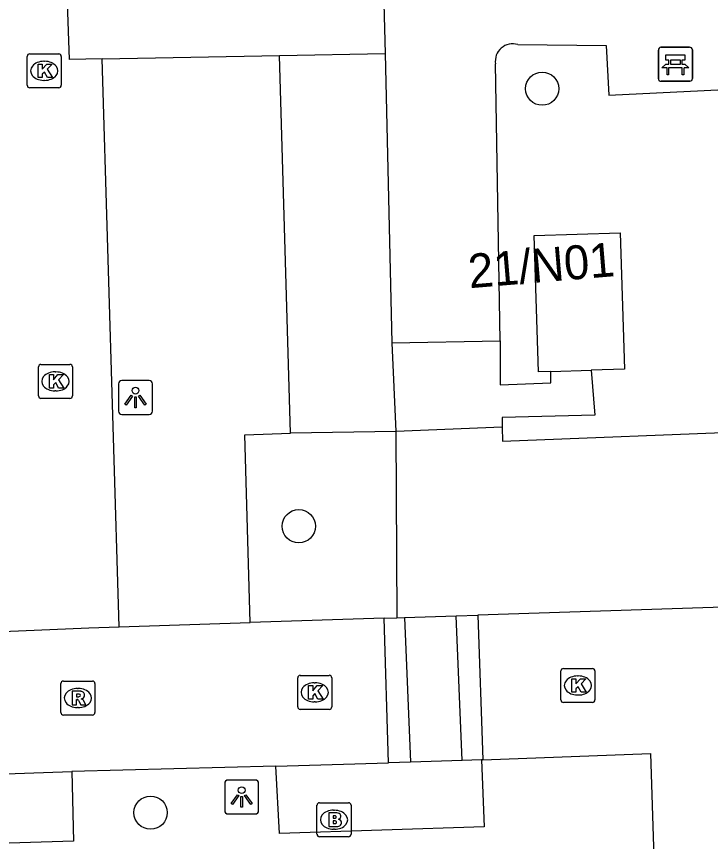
# Model space of a CAD drawing. Extents: x 162250 to 162654, y 380744 to 381605.
# Drawn here: x 162372.82 to 162393.23, y 381114.47 to 381138.73 of the extents above; entities that cross this region are included whole.
import ezdxf

# ---------------------------------------------------------------- set-up
doc = ezdxf.new("R2010")
doc.units = 0
for name, color, linetype in [('IMGEO_Bank', 7, 'Continuous'), ('IMGEO_Boom', 7, 'Continuous'), ('IMGEO_Brandkraan', 7, 'Continuous'), ('IMGEO_Groenvoorziening', 7, 'Continuous'), ('IMGEO_Kolk', 7, 'Continuous'), ('IMGEO_Lichtpunt', 7, 'Continuous'), ('IMGEO_Pand', 7, 'Continuous'), ('IMGEO_Pand_nummerreeks', 7, 'Continuous'), ('IMGEO_Parkeervlak_open', 7, 'Continuous'), ('IMGEO_Rioolput', 7, 'Continuous'), ('IMGEO_Voetpad_gesloten', 7, 'Continuous'), ('IMGEO_Voetpad_open', 7, 'Continuous'), ('IMGEO_Woonerf_open', 7, 'Continuous')]:
    doc.layers.add(name, color=color, linetype=linetype)

msp = doc.modelspace()

# ---------------------------------------------------------------- linework, layer by layer
at = {"layer": 'IMGEO_Bank'}
for p, q in [((162391.773, 381137.826), (162392.614, 381137.826)), ((162392.614, 381137.826), (162391.773, 381137.826)), ((162391.698, 381136.901), (162391.698, 381137.742)), ((162391.698, 381137.742), (162391.698, 381136.901)), ((162392.698, 381137.751), (162392.698, 381136.91)), ((162392.698, 381136.91), (162392.698, 381137.751)), ((162392.007, 381137.332), (162392.007, 381137.438)), ((162392.051, 381137.438), (162392.051, 381137.332)), ((162392.339, 381137.444), (162392.057, 381137.444)), ((162392.057, 381137.326), (162392.339, 381137.326)), ((162392.345, 381137.332), (162392.345, 381137.438)), ((162392.389, 381137.438), (162392.389, 381137.332)), ((162392.395, 381137.224), (162392.002, 381137.224)), ((162392.623, 381136.826), (162391.782, 381136.826)), ((162391.782, 381136.826), (162392.623, 381136.826))]:
    msp.add_line(p, q, dxfattribs=at)
for points in [[(162392.001, 381137.444), (162391.915, 381137.444), (162391.915, 381137.605), (162392.478, 381137.605), (162392.478, 381137.444), (162392.395, 381137.444)], [(162391.945, 381137.224), (162391.803, 381137.224), (162391.915, 381137.326), (162392.001, 381137.326)], [(162392.395, 381137.326), (162392.478, 381137.326), (162392.59, 381137.224), (162392.451, 381137.224)], [(162391.995, 381137.217), (162391.995, 381137.01), (162391.952, 381137.01), (162391.952, 381137.217)], [(162392.445, 381137.217), (162392.445, 381137.01), (162392.401, 381137.01), (162392.401, 381137.217)]]:
    msp.add_lwpolyline(points, dxfattribs=at)
for centre, radius, start, end in [((162391.776, 381137.748), 0.0779, 92.4484, 184.2845), ((162391.776, 381137.748), 0.0779, 92.4484, 184.2845), ((162392.62, 381137.748), 0.0779, 2.4484, 94.2845), ((162392.62, 381137.748), 0.0779, 2.4484, 94.2845), ((162392, 381137.437), 0.00671, 2.8957, 87.1043), ((162392, 381137.333), 0.00671, 272.8957, 357.1043), ((162392.057, 381137.437), 0.00671, 92.8957, 177.1043), ((162392.057, 381137.333), 0.00671, 182.8957, 267.1043), ((162392.339, 381137.437), 0.00671, 2.8957, 87.1043), ((162392.339, 381137.333), 0.00671, 272.8957, 357.1043), ((162392.396, 381137.437), 0.00671, 92.8957, 177.1043), ((162392.396, 381137.333), 0.00671, 182.8957, 267.1043), ((162391.945, 381137.217), 0.00671, 2.8957, 87.1043), ((162392.002, 381137.217), 0.00671, 92.8957, 177.1043), ((162392.394, 381137.217), 0.00671, 2.8957, 87.1043), ((162392.451, 381137.217), 0.00671, 92.8957, 177.1043), ((162391.776, 381136.904), 0.0779, 182.4484, 274.2845), ((162391.776, 381136.904), 0.0779, 182.4484, 274.2845), ((162392.62, 381136.904), 0.0779, 272.4484, 4.2845), ((162392.62, 381136.904), 0.0779, 272.4484, 4.2845)]:
    msp.add_arc(centre, radius, start, end, dxfattribs=at)
at = {"layer": 'IMGEO_Boom'}
for centre in [(162388.281, 381136.607), (162381.124, 381123.738), (162376.767, 381115.316)]:
    msp.add_circle(centre, 0.489, dxfattribs=at)
at = {"layer": 'IMGEO_Brandkraan'}
for p, q in [((162381.66, 381114.681), (162381.66, 381115.533)), ((162381.735, 381115.607), (162382.587, 381115.607)), ((162382.661, 381115.533), (162382.661, 381114.681)), ((162382.148, 381115.387), (162382.173, 381115.387)), ((162382.171, 381114.827), (162382.146, 381114.827)), ((162382.587, 381114.607), (162381.735, 381114.607))]:
    msp.add_line(p, q, dxfattribs=at)
for points in [[(162381.66, 381114.681), (162381.66, 381115.533)], [(162381.735, 381115.607), (162382.587, 381115.607)], [(162382.661, 381115.533), (162382.661, 381114.681)], [(162382.008, 381115.307), (162382.008, 381114.907), (162382.221, 381114.907)], [(162382.239, 381115.307), (162382.008, 381115.307)], [(162382.187, 381115.226), (162382.133, 381115.226), (162382.133, 381115.15)], [(162382.133, 381115.15), (162382.186, 381115.15)], [(162382.195, 381115.074), (162382.133, 381115.074), (162382.133, 381114.993)], [(162382.133, 381114.993), (162382.195, 381114.993)], [(162382.587, 381114.607), (162381.735, 381114.607)]]:
    msp.add_lwpolyline(points, dxfattribs=at)
for centre, radius, start, end in [((162381.737, 381115.531), 0.0765, 91.552, 178.448), ((162381.737, 381115.531), 0.0765, 91.552, 178.448), ((162382.585, 381115.531), 0.0765, 1.552, 88.448), ((162382.585, 381115.531), 0.0765, 1.552, 88.448), ((162382.243, 381115.162), 0.145, 59.4692, 91.5367), ((162382.268, 381115.209), 0.0922, 285.5137, 58.1501), ((162382.188, 381115.188), 0.0379, 267.8285, 90.9355), ((162382.196, 381115.033), 0.0404, 269.8759, 90.5077), ((162382.273, 381115.017), 0.105, 301.3115, 78.989), ((162382.227, 381115.158), 0.251, 268.6676, 293.5347), ((162381.737, 381114.683), 0.0765, 181.552, 268.448), ((162381.737, 381114.683), 0.0765, 181.552, 268.448), ((162382.585, 381114.683), 0.0765, 271.552, 358.448), ((162382.585, 381114.683), 0.0765, 271.552, 358.448)]:
    msp.add_arc(centre, radius, start, end, dxfattribs=at)
for centre, major_axis, ratio, start_param, end_param in [((162382.147, 381115.107), (-0.387, 0.002), 0.722429, 4.712389, 7.853982), ((162382.172, 381115.107), (-0.39, 0.002), 0.717154, 1.570796, 4.712389)]:
    msp.add_ellipse(centre, major_axis=major_axis, ratio=ratio, start_param=start_param, end_param=end_param, dxfattribs=at)
at = {"layer": 'IMGEO_Groenvoorziening'}
msp.add_lwpolyline([(162383.975, 381126.528), (162380.885, 381126.473)], dxfattribs=at)
at = {"layer": 'IMGEO_Kolk'}
for p, q in [((162373.214, 381137.632), (162374.066, 381137.632)), ((162373.139, 381136.706), (162373.139, 381137.558)), ((162373.627, 381137.412), (162373.652, 381137.412)), ((162374.14, 381137.558), (162374.14, 381136.706)), ((162373.65, 381136.852), (162373.625, 381136.852)), ((162374.066, 381136.632), (162373.214, 381136.632)), ((162373.47, 381127.572), (162373.47, 381128.424)), ((162373.545, 381128.498), (162374.397, 381128.498)), ((162374.471, 381128.424), (162374.471, 381127.572)), ((162373.958, 381128.278), (162373.983, 381128.278)), ((162373.981, 381127.718), (162373.956, 381127.718)), ((162374.397, 381127.498), (162373.545, 381127.498)), ((162388.831, 381118.63), (162388.831, 381119.482)), ((162388.906, 381119.556), (162389.758, 381119.556)), ((162389.832, 381119.482), (162389.832, 381118.63)), ((162381.093, 381118.428), (162381.093, 381119.28)), ((162381.168, 381119.354), (162382.02, 381119.354)), ((162381.581, 381119.134), (162381.606, 381119.134)), ((162382.094, 381119.28), (162382.094, 381118.428)), ((162389.319, 381119.336), (162389.344, 381119.336)), ((162389.342, 381118.776), (162389.317, 381118.776)), ((162381.604, 381118.574), (162381.579, 381118.574)), ((162389.758, 381118.556), (162388.906, 381118.556)), ((162382.02, 381118.354), (162381.168, 381118.354))]:
    msp.add_line(p, q, dxfattribs=at)
for points in [[(162373.214, 381137.632), (162374.066, 381137.632)], [(162373.139, 381136.706), (162373.139, 381137.558)], [(162373.46, 381137.332), (162373.583, 381137.332), (162373.583, 381137.181), (162373.713, 381137.332), (162373.877, 381137.332), (162373.731, 381137.181), (162373.884, 381136.932), (162373.732, 381136.932), (162373.647, 381137.096), (162373.583, 381137.029), (162373.583, 381136.932), (162373.46, 381136.932), (162373.46, 381137.332)], [(162374.14, 381137.558), (162374.14, 381136.706)], [(162374.066, 381136.632), (162373.214, 381136.632)], [(162373.47, 381127.572), (162373.47, 381128.424)], [(162373.545, 381128.498), (162374.397, 381128.498)], [(162374.471, 381128.424), (162374.471, 381127.572)], [(162373.791, 381128.198), (162373.914, 381128.198), (162373.914, 381128.047), (162374.044, 381128.198), (162374.208, 381128.198), (162374.062, 381128.047), (162374.215, 381127.798), (162374.063, 381127.798), (162373.978, 381127.962), (162373.914, 381127.895), (162373.914, 381127.798), (162373.791, 381127.798), (162373.791, 381128.198)], [(162374.397, 381127.498), (162373.545, 381127.498)], [(162388.831, 381118.63), (162388.831, 381119.482)], [(162388.906, 381119.556), (162389.758, 381119.556)], [(162389.832, 381119.482), (162389.832, 381118.63)], [(162381.093, 381118.428), (162381.093, 381119.28)], [(162381.168, 381119.354), (162382.02, 381119.354)], [(162382.094, 381119.28), (162382.094, 381118.428)], [(162389.152, 381119.256), (162389.275, 381119.256), (162389.275, 381119.105), (162389.405, 381119.256), (162389.569, 381119.256), (162389.423, 381119.105), (162389.576, 381118.856), (162389.424, 381118.856), (162389.339, 381119.02), (162389.275, 381118.953), (162389.275, 381118.856), (162389.152, 381118.856), (162389.152, 381119.256)], [(162381.414, 381119.054), (162381.537, 381119.054), (162381.537, 381118.903), (162381.667, 381119.054), (162381.831, 381119.054), (162381.685, 381118.903), (162381.838, 381118.654), (162381.686, 381118.654), (162381.601, 381118.818), (162381.537, 381118.751), (162381.537, 381118.654), (162381.414, 381118.654), (162381.414, 381119.054)], [(162389.758, 381118.556), (162388.906, 381118.556)], [(162382.02, 381118.354), (162381.168, 381118.354)]]:
    msp.add_lwpolyline(points, dxfattribs=at)
for centre, start, end in [((162373.216, 381137.556), 91.552, 178.448), ((162373.216, 381137.556), 91.552, 178.448), ((162374.064, 381137.556), 1.552, 88.448), ((162374.064, 381137.556), 1.552, 88.448), ((162373.216, 381136.708), 181.552, 268.448), ((162373.216, 381136.708), 181.552, 268.448), ((162374.064, 381136.708), 271.552, 358.448), ((162374.064, 381136.708), 271.552, 358.448), ((162373.547, 381128.422), 91.552, 178.448), ((162373.547, 381128.422), 91.552, 178.448), ((162374.395, 381128.422), 1.552, 88.448), ((162374.395, 381128.422), 1.552, 88.448), ((162373.547, 381127.574), 181.552, 268.448), ((162373.547, 381127.574), 181.552, 268.448), ((162374.395, 381127.574), 271.552, 358.448), ((162374.395, 381127.574), 271.552, 358.448), ((162388.908, 381119.48), 91.552, 178.448), ((162388.908, 381119.48), 91.552, 178.448), ((162389.756, 381119.48), 1.552, 88.448), ((162389.756, 381119.48), 1.552, 88.448), ((162381.17, 381119.278), 91.552, 178.448), ((162381.17, 381119.278), 91.552, 178.448), ((162382.018, 381119.278), 1.552, 88.448), ((162382.018, 381119.278), 1.552, 88.448), ((162381.17, 381118.43), 181.552, 268.448), ((162381.17, 381118.43), 181.552, 268.448), ((162382.018, 381118.43), 271.552, 358.448), ((162382.018, 381118.43), 271.552, 358.448), ((162388.908, 381118.632), 181.552, 268.448), ((162388.908, 381118.632), 181.552, 268.448), ((162389.756, 381118.632), 271.552, 358.448), ((162389.756, 381118.632), 271.552, 358.448)]:
    msp.add_arc(centre, 0.0765, start, end, dxfattribs=at)
for centre, major_axis, ratio, start_param, end_param in [((162373.626, 381137.132), (-0.387, 0.002), 0.722429, 4.712389, 7.853982), ((162373.651, 381137.132), (-0.39, 0.002), 0.717154, 1.570796, 4.712389), ((162373.957, 381127.998), (-0.387, 0.002), 0.722429, 4.712389, 7.853982), ((162373.982, 381127.998), (-0.39, 0.002), 0.717154, 1.570796, 4.712389), ((162381.58, 381118.854), (-0.387, 0.002), 0.722429, 4.712389, 7.853982), ((162381.605, 381118.854), (-0.39, 0.002), 0.717154, 1.570796, 4.712389), ((162389.318, 381119.056), (-0.387, 0.002), 0.722429, 4.712389, 7.853982), ((162389.343, 381119.056), (-0.39, 0.002), 0.717154, 1.570796, 4.712389)]:
    msp.add_ellipse(centre, major_axis=major_axis, ratio=ratio, start_param=start_param, end_param=end_param, dxfattribs=at)
at = {"layer": 'IMGEO_Lichtpunt'}
for p, q in [((162375.825, 381127.929), (162375.825, 381127.122)), ((162375.825, 381127.929), (162375.825, 381127.122)), ((162376.727, 381128.024), (162375.919, 381128.024)), ((162376.727, 381128.024), (162375.919, 381128.024)), ((162376.821, 381127.122), (162376.821, 381127.929)), ((162376.821, 381127.122), (162376.821, 381127.929)), ((162375.919, 381127.028), (162376.727, 381127.028)), ((162375.919, 381127.028), (162376.727, 381127.028)), ((162379.849, 381116.275), (162379.041, 381116.275)), ((162379.849, 381116.275), (162379.041, 381116.275)), ((162378.947, 381116.18), (162378.947, 381115.373)), ((162378.947, 381116.18), (162378.947, 381115.373)), ((162379.943, 381115.373), (162379.943, 381116.18)), ((162379.943, 381115.373), (162379.943, 381116.18)), ((162379.041, 381115.279), (162379.849, 381115.279)), ((162379.041, 381115.279), (162379.849, 381115.279))]:
    msp.add_line(p, q, dxfattribs=at)
for points in [[(162376.199, 381127.593), (162376.238, 381127.565), (162376.05, 381127.303), (162376.012, 381127.33), (162376.199, 381127.593)], [(162376.301, 381127.545), (162376.348, 381127.545), (162376.348, 381127.223), (162376.301, 381127.223), (162376.301, 381127.545)], [(162376.411, 381127.565), (162376.449, 381127.592), (162376.636, 381127.33), (162376.597, 381127.302), (162376.411, 381127.565)], [(162379.321, 381115.844), (162379.36, 381115.816), (162379.172, 381115.554), (162379.134, 381115.581), (162379.321, 381115.844)], [(162379.423, 381115.796), (162379.47, 381115.796), (162379.47, 381115.474), (162379.423, 381115.474), (162379.423, 381115.796)], [(162379.533, 381115.816), (162379.571, 381115.843), (162379.758, 381115.581), (162379.719, 381115.553), (162379.533, 381115.816)]]:
    msp.add_lwpolyline(points, dxfattribs=at)
for centre in [(162376.324, 381127.727), (162379.446, 381115.978)]:
    msp.add_circle(centre, 0.0994, dxfattribs=at)
for centre, start, end in [((162375.919, 381127.929), 90, 180), ((162375.919, 381127.929), 90, 180), ((162376.727, 381127.929), 0, 90), ((162376.727, 381127.929), 0, 90), ((162375.919, 381127.122), 180, 270), ((162375.919, 381127.122), 180, 270), ((162376.727, 381127.122), 270, 0), ((162376.727, 381127.122), 270, 360), ((162379.041, 381116.18), 90, 180), ((162379.041, 381116.18), 90, 180), ((162379.849, 381116.18), 0, 90), ((162379.849, 381116.18), 0, 90), ((162379.041, 381115.373), 180, 270), ((162379.041, 381115.373), 180, 270), ((162379.849, 381115.373), 270, 0), ((162379.849, 381115.373), 270, 360)]:
    msp.add_arc(centre, 0.0946, start, end, dxfattribs=at)
at = {"layer": 'IMGEO_Pand'}
for points in [[(162388.535, 381128.29), (162388.172, 381128.279), (162388.045, 381132.292), (162390.576, 381132.372), (162390.703, 381128.358), (162389.723, 381128.327)], [(162388.535, 381128.29), (162389.723, 381128.327)]]:
    msp.add_lwpolyline(points, dxfattribs=at)
at = {"layer": 'IMGEO_Parkeervlak_open'}
for points in [[(162380.885, 381126.473), (162380.554, 381137.585)], [(162375.842, 381120.781), (162375.345, 381137.488)], [(162387.106, 381126.653), (162387.113, 381126.237), (162402.073, 381126.826)], [(162379.694, 381120.907), (162379.538, 381126.427), (162380.885, 381126.473)], [(162383.975, 381126.528), (162384.005, 381121.048)], [(162401.426, 381121.617), (162386.393, 381121.126)], [(162384.234, 381121.055), (162385.748, 381121.105)], [(162385.748, 381121.105), (162386.393, 381121.126)], [(162375.842, 381120.781), (162379.694, 381120.907)], [(162384.005, 381121.048), (162384.234, 381121.055)], [(162380.448, 381116.685), (162383.758, 381116.785)], [(162384.408, 381116.804), (162383.758, 381116.785)], [(162385.931, 381116.85), (162384.408, 381116.804)], [(162386.5, 381116.867), (162385.931, 381116.85)], [(162369.712, 381116.357), (162374.447, 381116.522)]]:
    msp.add_lwpolyline(points, dxfattribs=at)
at = {"layer": 'IMGEO_Rioolput'}
for p, q in [((162374.204, 381119.186), (162375.056, 381119.186)), ((162374.129, 381118.26), (162374.129, 381119.112)), ((162374.617, 381118.966), (162374.642, 381118.966)), ((162375.13, 381119.112), (162375.13, 381118.26)), ((162374.64, 381118.406), (162374.615, 381118.406)), ((162375.056, 381118.186), (162374.204, 381118.186))]:
    msp.add_line(p, q, dxfattribs=at)
for points in [[(162374.204, 381119.186), (162375.056, 381119.186)], [(162374.129, 381118.26), (162374.129, 381119.112)], [(162374.718, 381118.884), (162374.466, 381118.886), (162374.466, 381118.486)], [(162375.13, 381119.112), (162375.13, 381118.26)], [(162374.466, 381118.486), (162374.59, 381118.486), (162374.59, 381118.648), (162374.601, 381118.648)], [(162374.644, 381118.805), (162374.59, 381118.805), (162374.59, 381118.724)], [(162374.59, 381118.724), (162374.642, 381118.724)], [(162374.648, 381118.619), (162374.719, 381118.486), (162374.859, 381118.486), (162374.794, 381118.612)], [(162375.056, 381118.186), (162374.204, 381118.186)]]:
    msp.add_lwpolyline(points, dxfattribs=at)
for centre, radius, start, end in [((162374.206, 381119.11), 0.0765, 91.552, 178.448), ((162374.206, 381119.11), 0.0765, 91.552, 178.448), ((162375.054, 381119.11), 0.0765, 1.552, 88.448), ((162375.054, 381119.11), 0.0765, 1.552, 88.448), ((162374.717, 381118.774), 0.109, 350.3612, 89.416), ((162374.6, 381118.595), 0.0533, 26.0293, 88.6989), ((162374.626, 381118.913), 0.19, 274.7715, 282.9687), ((162374.65, 381118.709), 0.0964, 77.0061, 93.1865), ((162374.664, 381118.766), 0.0378, 276.6634, 79.6772), ((162374.715, 381118.774), 0.112, 277.5842, 350.9817), ((162374.699, 381118.559), 0.108, 29.5134, 73.7905), ((162374.206, 381118.262), 0.0765, 181.552, 268.448), ((162374.206, 381118.262), 0.0765, 181.552, 268.448), ((162375.054, 381118.262), 0.0765, 271.552, 358.448), ((162375.054, 381118.262), 0.0765, 271.552, 358.448)]:
    msp.add_arc(centre, radius, start, end, dxfattribs=at)
for centre, major_axis, ratio, start_param, end_param in [((162374.616, 381118.686), (-0.387, 0.002), 0.722429, 4.712389, 7.853982), ((162374.641, 381118.686), (-0.39, 0.002), 0.717154, 1.570796, 4.712389)]:
    msp.add_ellipse(centre, major_axis=major_axis, ratio=ratio, start_param=start_param, end_param=end_param, dxfattribs=at)
at = {"layer": 'IMGEO_Voetpad_gesloten'}
for points in [[(162383.599, 381140.226), (162383.661, 381137.643)], [(162387.564, 381137.904), (162390.166, 381137.88), (162390.243, 381136.417), (162397.246, 381136.763), (162397.189, 381138.232), (162401.842, 381138.323)], [(162383.661, 381137.643), (162383.865, 381129.129)], [(162387.046, 381129.195), (162386.909, 381137.336)], [(162383.865, 381129.129), (162387.046, 381129.195)]]:
    msp.add_lwpolyline(points, dxfattribs=at)
msp.add_arc((162387.413, 381137.416), 0.511, 72.8501, 189.012, dxfattribs=at)
at = {"layer": 'IMGEO_Voetpad_open'}
for points in [[(162375.345, 381137.488), (162374.38, 381137.47), (162374.295, 381139.976)], [(162375.345, 381137.488), (162380.554, 381137.585)], [(162380.554, 381137.585), (162383.661, 381137.643)], [(162383.865, 381129.129), (162383.975, 381126.528)], [(162387.046, 381129.195), (162387.046, 381127.9), (162388.537, 381127.957), (162388.535, 381128.29)], [(162389.723, 381128.327), (162389.827, 381127.01), (162387.102, 381126.937), (162387.106, 381126.653)], [(162387.106, 381126.653), (162383.975, 381126.528)], [(162386.541, 381116.869), (162391.47, 381117.053), (162391.565, 381114.004)], [(162386.5, 381116.867), (162386.571, 381114.901), (162380.553, 381114.699), (162380.448, 381116.685)], [(162386.541, 381116.869), (162386.5, 381116.867)], [(162374.447, 381116.522), (162374.504, 381114.474), (162356.514, 381113.92), (162356.462, 381115.897)], [(162380.448, 381116.685), (162374.447, 381116.522)]]:
    msp.add_lwpolyline(points, dxfattribs=at)
at = {"layer": 'IMGEO_Woonerf_open'}
for points in [[(162385.931, 381116.85), (162385.748, 381121.105)], [(162386.393, 381121.126), (162386.541, 381116.869)], [(162383.633, 381121.036), (162379.694, 381120.907)], [(162383.633, 381121.036), (162384.005, 381121.048)], [(162383.758, 381116.785), (162383.633, 381121.036)], [(162384.234, 381121.055), (162384.408, 381116.804)], [(162371.488, 381120.602), (162374.95, 381120.752), (162375.842, 381120.781)]]:
    msp.add_lwpolyline(points, dxfattribs=at)

# ---------------------------------------------------------------- texts
at = {"layer": 'IMGEO_Pand_nummerreeks'}
msp.add_text('21/N01', height=1, rotation=4.7636, dxfattribs=at).set_placement((162386.147, 381130.738))

doc.saveas('drawing.dxf')
